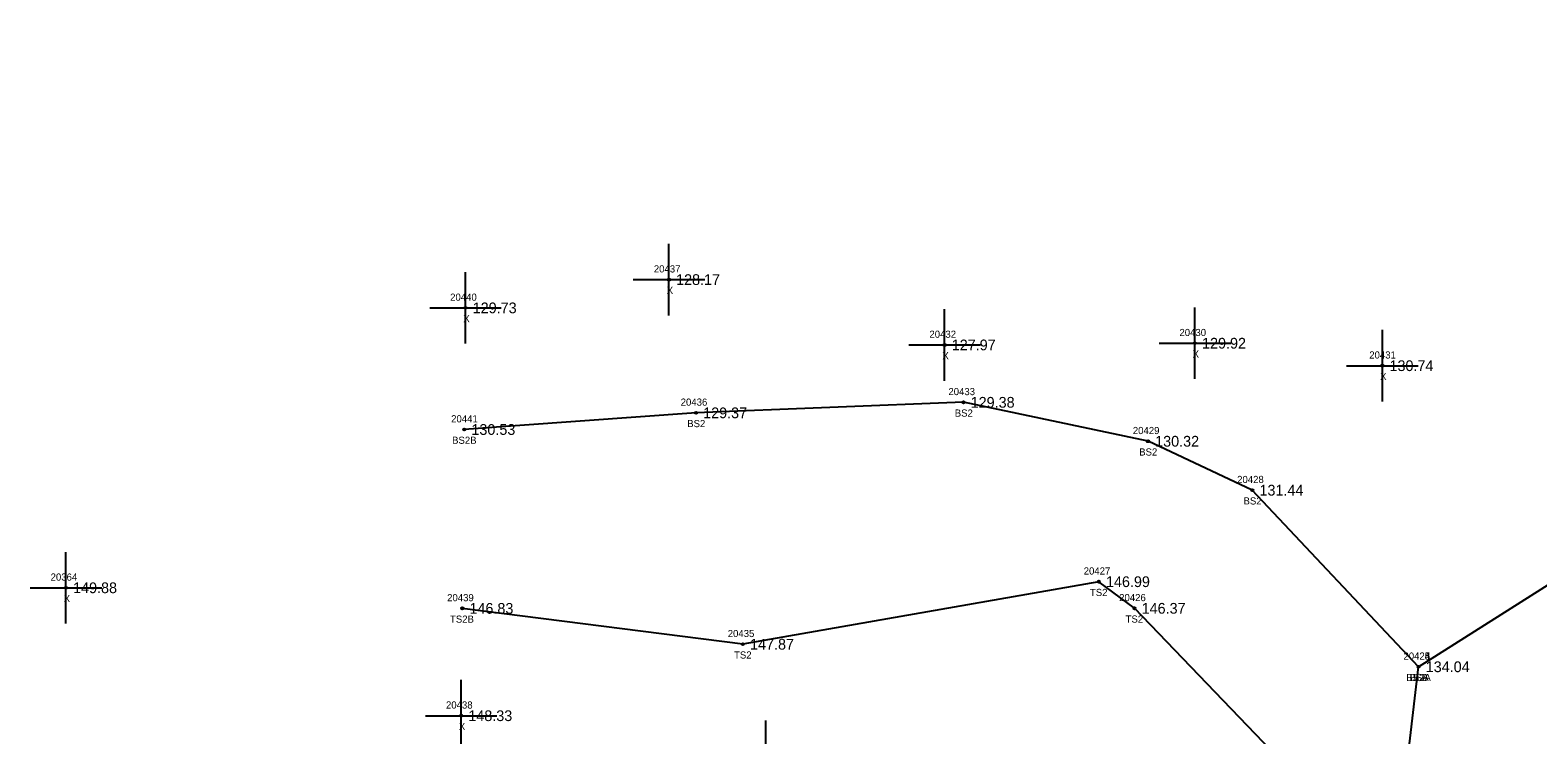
# Model space of a CAD drawing. Extents: x 2449605 to 2452431, y 1012876 to 1014922.
# Drawn here: x 2450541.6 to 2450752.2, y 1013760.1 to 1013858.6 of the extents above; entities that cross this region are included whole.
import ezdxf

# ---------------------------------------------------------------- set-up
doc = ezdxf.new("R2010")
doc.units = 0
for name, color, linetype in [('RD_DTM_BkLn1', 7, 'Continuous'), ('RD_DTM_BkLn2', 7, 'Continuous'), ('RD_DTM_BkLn_txCode', 7, 'Continuous'), ('RD_EX_Misc', 7, 'Continuous'), ('RD_EX_Misc_txCode', 7, 'Continuous'), ('RD_EX_TX_Misc_ELEV', 7, 'Continuous'), ('RD_SMD_Locator', 7, 'Continuous')]:
    doc.layers.add(name, color=color, linetype=linetype)

msp = doc.modelspace()

# ---------------------------------------------------------------- linework, layer by layer
at = {"layer": 'RD_DTM_BkLn1'}
msp.add_line((2450733.94, 1013756.08), (2450735.55, 1013769.66), dxfattribs=at)
at = {"layer": 'RD_DTM_BkLn2'}
for points in [[(2450735.55, 1013769.66), (2450799.36, 1013810.09), (2450876.73, 1013859.53), (2450898.26, 1013876.5), (2450920.65, 1013868.96)], [(2450735.55, 1013769.66), (2450712.33, 1013794.34), (2450697.76, 1013801.18), (2450671.99, 1013806.62), (2450634.63, 1013805.15), (2450602.26, 1013802.82)], [(2450722.94, 1013749.68), (2450695.87, 1013777.83), (2450690.89, 1013781.55), (2450641.18, 1013772.81), (2450601.99, 1013777.82)]]:
    msp.add_lwpolyline(points, dxfattribs=at)
at = {"layer": 'RD_EX_Misc'}
for p, q in [((2450630.85, 1013818.77), (2450630.85, 1013828.77)), ((2450602.44, 1013814.82), (2450602.44, 1013824.82)), ((2450625.85, 1013823.77), (2450635.85, 1013823.77)), ((2450597.44, 1013819.82), (2450607.44, 1013819.82)), ((2450669.35, 1013809.64), (2450669.35, 1013819.64)), ((2450704.31, 1013809.88), (2450704.31, 1013819.88)), ((2450730.49, 1013806.74), (2450730.49, 1013816.74)), ((2450664.35, 1013814.64), (2450674.35, 1013814.64)), ((2450699.31, 1013814.88), (2450709.31, 1013814.88)), ((2450725.49, 1013811.74), (2450735.49, 1013811.74)), ((2450546.63, 1013775.7), (2450546.63, 1013785.7)), ((2450541.63, 1013780.7), (2450551.63, 1013780.7)), ((2450601.83, 1013757.82), (2450601.83, 1013767.82)), ((2450596.83, 1013762.82), (2450606.83, 1013762.82)), ((2450644.36, 1013752.14), (2450644.36, 1013762.14))]:
    msp.add_line(p, q, dxfattribs=at)
at = {"layer": 'RD_SMD_Locator'}
for centre in [(2450630.85, 1013823.77), (2450602.44, 1013819.82), (2450669.35, 1013814.64), (2450704.31, 1013814.88), (2450730.49, 1013811.74), (2450671.99, 1013806.62), (2450634.63, 1013805.15), (2450602.26, 1013802.82), (2450697.76, 1013801.18), (2450712.33, 1013794.34), (2450690.89, 1013781.55), (2450546.63, 1013780.7), (2450601.99, 1013777.82), (2450695.87, 1013777.83), (2450641.18, 1013772.81), (2450735.55, 1013769.66), (2450735.55, 1013769.66), (2450735.55, 1013769.66), (2450601.83, 1013762.82)]:
    msp.add_circle(centre, 0.15, dxfattribs=at)

# ---------------------------------------------------------------- texts
at = {"layer": 'RD_DTM_BkLn_txCode'}
for s, p in [('20436', (2450632.49, 1013806.15)), ('20433', (2450669.88, 1013807.62)), ('20441', (2450600.43, 1013803.82)), ('BS2', (2450670.77, 1013804.62)), ('BS2', (2450633.4, 1013803.15)), ('20429', (2450695.64, 1013802.18)), ('BS2B', (2450600.56, 1013800.82)), ('BS2', (2450696.53, 1013799.18)), ('20428', (2450710.21, 1013795.34)), ('BS2', (2450711.1, 1013792.34)), ('20427', (2450688.78, 1013782.55)), ('20439', (2450599.87, 1013778.82)), ('TS2', (2450689.65, 1013779.55)), ('20426', (2450693.73, 1013778.83)), ('TS2B', (2450600.27, 1013775.82)), ('TS2', (2450694.63, 1013775.83)), ('20435', (2450639.06, 1013773.81)), ('TS2', (2450639.94, 1013770.81)), ('20423', (2450733.44, 1013770.66)), ('20424', (2450733.44, 1013770.66)), ('20425', (2450733.44, 1013770.66)), ('BS2A', (2450733.84, 1013767.66)), ('BSA', (2450734.29, 1013767.66)), ('BLB', (2450734.33, 1013767.66))]:
    msp.add_text(s, height=1, dxfattribs=at).set_placement(p)
at = {"layer": 'RD_EX_Misc_txCode'}
for s, p in [('20437', (2450628.74, 1013824.77)), ('20440', (2450600.29, 1013820.82)), ('X', (2450630.54, 1013821.77)), ('X', (2450602.13, 1013817.82)), ('20432', (2450667.23, 1013815.64)), ('20430', (2450702.15, 1013815.88)), ('X', (2450669.04, 1013812.64)), ('X', (2450703.99, 1013812.88)), ('20431', (2450728.66, 1013812.74)), ('X', (2450730.18, 1013809.74)), ('20364', (2450544.49, 1013781.7)), ('X', (2450546.32, 1013778.7)), ('20438', (2450599.71, 1013763.82)), ('X', (2450601.51, 1013760.82))]:
    msp.add_text(s, height=1, dxfattribs=at).set_placement(p)
at = {"layer": 'RD_EX_TX_Misc_ELEV'}
for s, p in [('128.17', (2450631.85, 1013823.02)), ('129.73', (2450603.44, 1013819.07)), ('127.97', (2450670.35, 1013813.89)), ('129.92', (2450705.31, 1013814.13)), ('130.74', (2450731.49, 1013810.99)), ('129.38', (2450672.99, 1013805.87)), ('129.37', (2450635.63, 1013804.4)), ('130.53', (2450603.26, 1013802.07)), ('130.32', (2450698.76, 1013800.43)), ('131.44', (2450713.33, 1013793.59)), ('149.88', (2450547.63, 1013779.95)), ('146.99', (2450691.89, 1013780.8)), ('146.83', (2450602.99, 1013777.07)), ('146.37', (2450696.87, 1013777.08)), ('147.87', (2450642.18, 1013772.06)), ('134.04', (2450736.55, 1013768.91)), ('134.04', (2450736.55, 1013768.91)), ('134.04', (2450736.55, 1013768.91)), ('148.33', (2450602.83, 1013762.07))]:
    msp.add_text(s, height=1.5, dxfattribs=at).set_placement(p)

doc.saveas('drawing.dxf')
